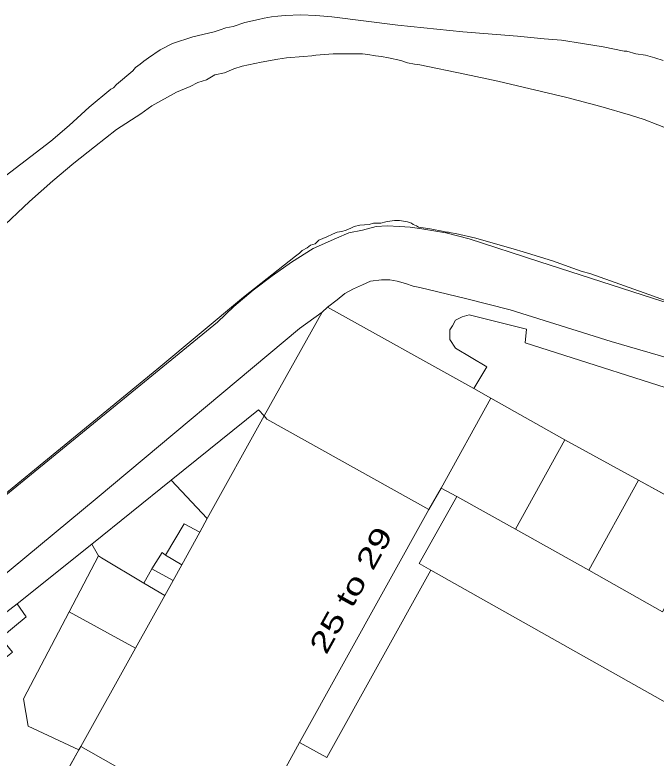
# Model space of a CAD drawing. Extents: x 528790 to 529292, y 179350 to 179856.
# Drawn here: x 528851.4 to 528898.3, y 179415.2 to 179469.6 of the extents above; entities that cross this region are included whole.
import ezdxf

# ---------------------------------------------------------------- set-up
doc = ezdxf.new("R2010")
doc.units = 0
doc.header["$LTSCALE"] = 0.6
doc.layers.add('1', color=7, linetype='Continuous', lineweight=13)
doc.layers.add('2', color=7, linetype='Continuous', lineweight=13)
doc.layers.add('5', color=7, linetype='Continuous')

msp = doc.modelspace()

# ---------------------------------------------------------------- linework, layer by layer
at = {"layer": '1'}
for points in [[(528849.6, 179457.05), (528854, 179460.4), (528855.35, 179461.55), (528856.8, 179462.9), (528858.4, 179464.2), (528858.6, 179464.3), (528858.8, 179464.55), (528860, 179465.55), (528860.2, 179465.8), (528860.55, 179466.05), (528860.8, 179466.25), (528861.15, 179466.5), (528862, 179467.1), (528862.9, 179467.55), (528864.4, 179468.05), (528865.95, 179468.4), (528866.4, 179468.55), (528866.8, 179468.7), (528867.35, 179468.8), (528868.2, 179469.1), (528869.2, 179469.3), (528869.6, 179469.4), (528870.15, 179469.5), (528870.6, 179469.55), (528871.15, 179469.6), (528872.3, 179469.65), (528873.4, 179469.6), (528874.55, 179469.5), (528879.4, 179468.9), (528884.15, 179468.4), (528888.15, 179468.1), (528890.1, 179467.9), (528891.35, 179467.8), (528892.9, 179467.55), (528894.4, 179467.3), (528895.95, 179467)], [(528873.4, 179466.7), (528873.1, 179466.65), (528872.5, 179466.6), (528871.25, 179466.5), (528870.6, 179466.4), (528869.4, 179466.2), (528868, 179465.9), (528867.4, 179465.7), (528866.7, 179465.4), (528866, 179465.25), (528865.4, 179464.9), (528864.75, 179464.7), (528864.2, 179464.4), (528863.2, 179464), (528861.4, 179463), (528860.6, 179462.4), (528858.8, 179461.25), (528857.2, 179460), (528855.7, 179458.8), (528854.15, 179457.5), (528852.45, 179456), (528850.2, 179453.9)], [(528899.4, 179461.2), (528897.4, 179462), (528896.4, 179462.3), (528894.25, 179462.95), (528891.75, 179463.6), (528886.7, 179464.8), (528884.3, 179465.3), (528881, 179466), (528880.6, 179466.05), (528880.1, 179466.15), (528879.6, 179466.3), (528878.7, 179466.5), (528878.2, 179466.6), (528877.75, 179466.65), (528877.2, 179466.75), (528876.8, 179466.8), (528874.65, 179466.8), (528873.4, 179466.7)], [(528895.95, 179467), (528896.15, 179467), (528896.8, 179466.8), (528897.5, 179466.7), (528898.2, 179466.5), (528898.8, 179466.3)], [(528798, 179391.4), (528866.2, 179447.15), (528867.4, 179448.3), (528868.8, 179449.5), (528870.2, 179450.55), (528871.6, 179451.55), (528873.2, 179452.55), (528874.9, 179453.3), (528875.8, 179453.7), (528876.8, 179453.9), (528877.8, 179454.15), (528878.6, 179454.2), (528879.5, 179454.15), (528880.3, 179454.1), (528881.15, 179454), (528882.9, 179453.7), (528884.6, 179453.25), (528889.7, 179451.6), (528898.1, 179448.9), (528906.55, 179446.2)], [(528906.55, 179446.2), (528898.1, 179448.9), (528889.7, 179451.6), (528884.6, 179453.25), (528882.9, 179453.7), (528881.15, 179454), (528880.3, 179454.1), (528879.5, 179454.15), (528878.6, 179454.2), (528877.8, 179454.15), (528876.8, 179453.9), (528875.8, 179453.7), (528874.9, 179453.3), (528873.2, 179452.55), (528871.6, 179451.55), (528870.2, 179450.55), (528868.8, 179449.5), (528867.4, 179448.3), (528866.2, 179447.15), (528798, 179391.4)], [(528844.2, 179429.3), (528853.5, 179436.9), (528861.75, 179443.7), (528868.1, 179449), (528871.9, 179452), (528872.2, 179452.2), (528872.4, 179452.4), (528872.75, 179452.6), (528873, 179452.8), (528873.35, 179452.9), (528873.6, 179453.15), (528874.2, 179453.4), (528874.6, 179453.6), (528874.95, 179453.75), (528875.3, 179453.8), (528875.6, 179453.9), (528875.95, 179454.05), (528876.2, 179454.15), (528876.6, 179454.25), (528877.3, 179454.3), (528877.6, 179454.4), (528878.15, 179454.4), (528878.5, 179454.5), (528878.8, 179454.55), (528879.15, 179454.6), (528879.5, 179454.6), (528880.1, 179454.5), (528880.4, 179454.4), (528880.5, 179454.3), (528880.75, 179454.2), (528880.9, 179454.1), (528881.743, 179453.978), (528882.75, 179453.8), (528882.95, 179453.75), (528883.1, 179453.75), (528883.3, 179453.7), (528883.6, 179453.65), (528885.1, 179453.3), (528887.9, 179452.5), (528888.55, 179452.3), (528890.7, 179451.65), (528892.8, 179450.9), (528893.5, 179450.7), (528898.1, 179449.05), (528899.1, 179448.7)], [(528845.8, 179424.7), (528857.4, 179434.3), (528872.2, 179446.7), (528873.85, 179447.9), (528874.25, 179448.25), (528874.95, 179448.8), (528875.5, 179449.25), (528876.15, 179449.6), (528876.8, 179449.9), (528877.4, 179450.15), (528878.2, 179450.25), (528878.8, 179450.25), (528879.35, 179450.15), (528879.95, 179450), (528880.5, 179449.8), (528881, 179449.7), (528884.35, 179448.9), (528887.6, 179448.05), (528895, 179445.75), (528899.95, 179444.3)], [(528899.95, 179444.3), (528895, 179445.75), (528887.6, 179448.05), (528884.35, 179448.9), (528881, 179449.7), (528880.5, 179449.8), (528879.95, 179450), (528879.35, 179450.15), (528878.8, 179450.25), (528878.2, 179450.25), (528877.4, 179450.15), (528876.8, 179449.9), (528876.15, 179449.6), (528875.5, 179449.25), (528874.95, 179448.8), (528874.25, 179448.25), (528884.95, 179442.3), (528885.9, 179443.9), (528883.6, 179445.25), (528883.5, 179445.4), (528883.3, 179445.75), (528883.2, 179445.9), (528883.2, 179446.6), (528883.4, 179446.9), (528883.6, 179447.3), (528884.1, 179447.55), (528884.6, 179447.7), (528888.8, 179446.65), (528888.7, 179445.65), (528915, 179437.25)], [(528915, 179437.25), (528888.7, 179445.65), (528888.8, 179446.65), (528884.6, 179447.7), (528884.1, 179447.55), (528883.6, 179447.3), (528883.4, 179446.9), (528883.2, 179446.6), (528883.2, 179445.9), (528883.3, 179445.75), (528883.5, 179445.4), (528883.6, 179445.25), (528885.9, 179443.9), (528884.95, 179442.3), (528886.2, 179441.6), (528891.6, 179438.55), (528897, 179435.6), (528902.35, 179432.65)], [(528898.75, 179425.95), (528893.35, 179429), (528888, 179432), (528883.7, 179434.4), (528880.95, 179429.5), (528881.8, 179429), (528901.688, 179417.809)], [(528854, 179412.2), (528856.05, 179415.85), (528852.35, 179417.6), (528852, 179419.6), (528855.35, 179425.95), (528857.5, 179430.05), (528857, 179430.9), (528851.55, 179426.55), (528852.2, 179425.6), (528850.35, 179424.05), (528851.2, 179423), (528846.8, 179419.5), (528845.2, 179421.5), (528842.1, 179419), (528837.3, 179415.2)], [(528901.688, 179417.809), (528881.8, 179429), (528874.2, 179415.3), (528872.2, 179416.4), (528869.2, 179410.9), (528869.95, 179410.5), (528868.9, 179408.6), (528868.6, 179408.7), (528866.8, 179405.2), (528867, 179405.1), (528865.9, 179403.2), (528865.2, 179403.6), (528862.4, 179398.6), (528864.35, 179397.55), (528855, 179380.05), (528875.6, 179368.55), (528875.15, 179367.6), (528877.1, 179366.4), (528880.6, 179364.55), (528882.5, 179363.4), (528883.2, 179364.4), (528897.956, 179356.024), (528905.826, 179356.024)]]:
    msp.add_lwpolyline(points, dxfattribs=at)
for points in [[(528881.65, 179433.45), (528882.55, 179435), (528886.2, 179441.6), (528884.95, 179442.3), (528874.25, 179448.25), (528873.85, 179447.9), (528869.6, 179440.3), (528869.8, 179440.05)], [(528869.6, 179440.3), (528873.85, 179447.9), (528872.2, 179446.7), (528857.4, 179434.3), (528845.8, 179424.7), (528845.4, 179424.4), (528845.2, 179424.15), (528845, 179423.8), (528844.8, 179423.4), (528844.75, 179423), (528844.8, 179422.6), (528844.8, 179422.2), (528845, 179421.8), (528845.2, 179421.5), (528849.6, 179425.05), (528851.55, 179426.55), (528857, 179430.9), (528862.8, 179435.6), (528869.2, 179440.75)], [(528888, 179432), (528891.6, 179438.55), (528886.2, 179441.6), (528882.55, 179435), (528883.7, 179434.4)], [(528862.8, 179435.6), (528865.45, 179432.8), (528869.6, 179440.3), (528869.2, 179440.75)], [(528868.6, 179408.7), (528868.9, 179408.6), (528869.95, 179410.5), (528869.2, 179410.9), (528872.2, 179416.4), (528881.65, 179433.45), (528869.8, 179440.05), (528869.6, 179440.3), (528865.45, 179432.8), (528864.9, 179431.8), (528863.6, 179429.4), (528862.95, 179428.25), (528862.35, 179427.15), (528860.2, 179423.3), (528856.2, 179416.1), (528868.2, 179409.3), (528867.95, 179409.1)], [(528891.6, 179438.55), (528888, 179432), (528893.35, 179429), (528897, 179435.6)], [(528864.9, 179431.8), (528865.45, 179432.8), (528862.8, 179435.6), (528857, 179430.9), (528857.5, 179430.05), (528857.7, 179429.9), (528860.8, 179428.05), (528861.4, 179429.1), (528862.15, 179430.3), (528862.4, 179430.1), (528863.75, 179432.4)], [(528902.35, 179432.65), (528897, 179435.6), (528893.35, 179429), (528898.75, 179425.95)], [(528881.8, 179429), (528880.95, 179429.5), (528883.7, 179434.4), (528882.55, 179435), (528881.65, 179433.45), (528872.2, 179416.4), (528874.2, 179415.3)], [(528863.75, 179432.4), (528862.4, 179430.1), (528863.6, 179429.4), (528864.9, 179431.8)], [(528862.95, 179428.25), (528863.6, 179429.4), (528862.4, 179430.1), (528862.15, 179430.3), (528861.4, 179429.1)], [(528860.2, 179423.3), (528862.35, 179427.15), (528860.8, 179428.05), (528857.7, 179429.9), (528857.5, 179430.05), (528855.35, 179425.95)], [(528862.35, 179427.15), (528862.95, 179428.25), (528861.4, 179429.1), (528860.8, 179428.05)], [(528849.6, 179425.05), (528850.35, 179424.05), (528852.2, 179425.6), (528851.55, 179426.55)], [(528855.35, 179425.95), (528852, 179419.6), (528852.35, 179417.6), (528856.05, 179415.85), (528856.2, 179416.1), (528860.2, 179423.3)], [(528853.8, 179411.8), (528865.8, 179405.1), (528866.1, 179405.55), (528866.8, 179405.2), (528868.6, 179408.7), (528867.95, 179409.1), (528868.2, 179409.3), (528856.2, 179416.1), (528856.05, 179415.85), (528854, 179412.2)]]:
    msp.add_lwpolyline(points, close=True, dxfattribs=at)
at = {"layer": '2'}
for p, q in [((528873.85, 179447.9), (528874.25, 179448.25)), ((528874.25, 179448.25), (528884.95, 179442.3)), ((528869.6, 179440.3), (528873.85, 179447.9)), ((528884.95, 179442.3), (528886.2, 179441.6)), ((528886.2, 179441.6), (528882.55, 179435)), ((528886.2, 179441.6), (528891.6, 179438.55)), ((528865.45, 179432.8), (528869.6, 179440.3)), ((528888, 179432), (528891.6, 179438.55)), ((528891.6, 179438.55), (528897, 179435.6)), ((528857, 179430.9), (528862.8, 179435.6)), ((528865.45, 179432.8), (528862.8, 179435.6)), ((528897, 179435.6), (528893.35, 179429)), ((528897, 179435.6), (528902.35, 179432.65)), ((528882.55, 179435), (528881.65, 179433.45)), ((528882.55, 179435), (528883.7, 179434.4)), ((528883.7, 179434.4), (528888, 179432)), ((528881.65, 179433.45), (528872.2, 179416.4)), ((528864.9, 179431.8), (528865.45, 179432.8)), ((528862.4, 179430.1), (528863.75, 179432.4)), ((528863.75, 179432.4), (528864.9, 179431.8)), ((528888, 179432), (528893.35, 179429)), ((528863.6, 179429.4), (528864.9, 179431.8)), ((528851.55, 179426.55), (528857, 179430.9)), ((528857, 179430.9), (528857.5, 179430.05)), ((528855.35, 179425.95), (528857.5, 179430.05)), ((528862.4, 179430.1), (528863.6, 179429.4)), ((528862.95, 179428.25), (528863.6, 179429.4)), ((528860.8, 179428.05), (528861.4, 179429.1)), ((528861.4, 179429.1), (528862.95, 179428.25)), ((528893.35, 179429), (528898.75, 179425.95)), ((528862.35, 179427.15), (528862.95, 179428.25)), ((528860.2, 179423.3), (528862.35, 179427.15)), ((528849.6, 179425.05), (528851.55, 179426.55)), ((528851.55, 179426.55), (528852.2, 179425.6)), ((528855.35, 179425.95), (528860.2, 179423.3)), ((528852.2, 179425.6), (528850.35, 179424.05)), ((528856.2, 179416.1), (528860.2, 179423.3)), ((528856.2, 179416.1), (528856.05, 179415.85)), ((528854, 179412.2), (528856.05, 179415.85))]:
    msp.add_line(p, q, dxfattribs=at)
for points in [[(528898.8, 179466.3), (528898.2, 179466.5), (528897.5, 179466.7), (528896.8, 179466.8), (528896.15, 179467), (528895.95, 179467), (528894.4, 179467.3), (528892.9, 179467.55), (528891.35, 179467.8), (528890.1, 179467.9), (528888.15, 179468.1), (528884.15, 179468.4), (528879.4, 179468.9), (528874.55, 179469.5), (528873.4, 179469.6), (528872.3, 179469.65), (528871.15, 179469.6), (528870.6, 179469.55), (528870.15, 179469.5), (528869.6, 179469.4), (528869.2, 179469.3), (528868.2, 179469.1), (528867.35, 179468.8), (528866.8, 179468.7), (528866.4, 179468.55), (528865.95, 179468.4), (528864.4, 179468.05), (528862.9, 179467.55), (528862, 179467.1), (528861.15, 179466.5), (528860.8, 179466.25), (528860.55, 179466.05), (528860.2, 179465.8), (528860, 179465.55), (528858.8, 179464.55), (528858.6, 179464.3), (528858.4, 179464.2), (528856.8, 179462.9), (528855.35, 179461.55), (528854, 179460.4), (528849.6, 179457.05)], [(528850.2, 179453.9), (528852.45, 179456), (528854.15, 179457.5), (528855.7, 179458.8), (528857.2, 179460), (528858.8, 179461.25), (528860.6, 179462.4), (528861.4, 179463), (528863.2, 179464), (528864.2, 179464.4), (528864.75, 179464.7), (528865.4, 179464.9), (528866, 179465.25), (528866.7, 179465.4), (528867.4, 179465.7), (528868, 179465.9), (528869.4, 179466.2), (528870.6, 179466.4), (528871.25, 179466.5), (528872.5, 179466.6), (528873.1, 179466.65), (528873.4, 179466.7), (528874.65, 179466.8), (528876.8, 179466.8), (528877.2, 179466.75), (528877.75, 179466.65), (528878.2, 179466.6), (528878.7, 179466.5), (528879.6, 179466.3), (528880.1, 179466.15), (528880.6, 179466.05), (528881, 179466), (528884.3, 179465.3), (528886.7, 179464.8), (528891.75, 179463.6), (528894.25, 179462.95), (528896.4, 179462.3), (528897.4, 179462), (528899.4, 179461.2)], [(528906.55, 179446.2), (528898.1, 179448.9), (528889.7, 179451.6), (528884.6, 179453.25), (528882.9, 179453.7), (528881.15, 179454), (528880.3, 179454.1), (528879.5, 179454.15), (528878.6, 179454.2), (528877.8, 179454.15), (528876.8, 179453.9), (528875.8, 179453.7), (528874.9, 179453.3), (528873.2, 179452.55), (528871.6, 179451.55), (528870.2, 179450.55), (528868.8, 179449.5), (528867.4, 179448.3), (528866.2, 179447.15), (528798, 179391.4), (528795.75, 179390.3), (528790.22, 179389.043)], [(528844.2, 179429.3), (528853.5, 179436.9), (528861.75, 179443.7), (528868.1, 179449), (528871.9, 179452), (528872.2, 179452.2), (528872.4, 179452.4), (528872.75, 179452.6), (528873, 179452.8), (528873.35, 179452.9), (528873.6, 179453.15), (528874.2, 179453.4), (528874.6, 179453.6), (528874.95, 179453.75), (528875.3, 179453.8), (528875.6, 179453.9), (528875.95, 179454.05), (528876.2, 179454.15), (528876.6, 179454.25), (528877.3, 179454.3), (528877.6, 179454.4), (528878.15, 179454.4), (528878.5, 179454.5), (528878.8, 179454.55), (528879.15, 179454.6), (528879.5, 179454.6), (528880.1, 179454.5), (528880.4, 179454.4), (528880.5, 179454.3), (528880.75, 179454.2), (528880.9, 179454.1), (528881.743, 179453.978), (528882.75, 179453.8), (528882.95, 179453.75), (528883.1, 179453.75), (528883.3, 179453.7), (528883.6, 179453.65), (528885.1, 179453.3), (528887.9, 179452.5), (528888.55, 179452.3), (528890.7, 179451.65), (528892.8, 179450.9), (528893.5, 179450.7), (528898.1, 179449.05), (528899.1, 179448.7)], [(528899.95, 179444.3), (528895, 179445.75), (528887.6, 179448.05), (528884.35, 179448.9), (528881, 179449.7), (528880.5, 179449.8), (528879.95, 179450), (528879.35, 179450.15), (528878.8, 179450.25), (528878.2, 179450.25), (528877.4, 179450.15), (528876.8, 179449.9), (528876.15, 179449.6), (528875.5, 179449.25), (528874.95, 179448.8), (528874.25, 179448.25)], [(528873.85, 179447.9), (528872.2, 179446.7), (528857.4, 179434.3), (528845.8, 179424.7), (528845.4, 179424.4), (528845.2, 179424.15), (528845, 179423.8), (528844.8, 179423.4), (528844.75, 179423), (528844.8, 179422.6), (528844.8, 179422.2), (528845, 179421.8), (528845.2, 179421.5)], [(528884.95, 179442.3), (528885.9, 179443.9), (528883.6, 179445.25), (528883.5, 179445.4), (528883.3, 179445.75), (528883.2, 179445.9), (528883.2, 179446.6), (528883.4, 179446.9), (528883.6, 179447.3), (528884.1, 179447.55), (528884.6, 179447.7), (528888.8, 179446.65), (528888.7, 179445.65), (528915, 179437.25)], [(528862.8, 179435.6), (528869.2, 179440.75), (528869.6, 179440.3)], [(528869.6, 179440.3), (528869.8, 179440.05), (528881.65, 179433.45)], [(528883.7, 179434.4), (528880.95, 179429.5), (528881.8, 179429)], [(528861.4, 179429.1), (528862.15, 179430.3), (528862.4, 179430.1)], [(528857.5, 179430.05), (528857.7, 179429.9), (528860.8, 179428.05), (528862.35, 179427.15)], [(528881.8, 179429), (528874.2, 179415.3), (528872.2, 179416.4)], [(528881.8, 179429), (528901.688, 179417.809), (528902.369, 179419.02), (528903.061, 179418.631), (528902.38, 179417.42), (528900.05, 179413.29), (528908.12, 179408.74), (528910.45, 179412.87), (528911.257, 179414.303), (528912.253, 179413.743), (528911.446, 179412.309), (528931.9, 179400.8)], [(528856.05, 179415.85), (528852.35, 179417.6), (528852, 179419.6), (528855.35, 179425.95)], [(528868.6, 179408.7), (528867.95, 179409.1), (528868.2, 179409.3), (528856.2, 179416.1)], [(528872.2, 179416.4), (528869.2, 179410.9), (528869.95, 179410.5), (528868.9, 179408.6), (528868.6, 179408.7)]]:
    msp.add_lwpolyline(points, dxfattribs=at)

# ---------------------------------------------------------------- texts
at = {"layer": '5', "width": 1.4}
msp.add_text('25 to 29', height=1.5, rotation=61, dxfattribs=at).set_placement((528874.15, 179422.75))

doc.saveas('drawing.dxf')
